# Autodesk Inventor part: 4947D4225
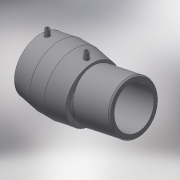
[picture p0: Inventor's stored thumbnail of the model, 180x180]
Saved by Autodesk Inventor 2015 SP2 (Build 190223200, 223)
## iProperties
Created: 2017-06
Part Number: 4947D4225
Material: Generic
Description: PLASSON ADJUSTABLE ELBOW (ONE SIDE) 225
Document SubType Name: Modeling
Designer: KIM
Mass: 8801.96 g
Surface Area: 6800.02 cm^2
Volume: 8801.96 cm^3
Density: 1 g/cm^3
Appearance: Default
Author: KIM
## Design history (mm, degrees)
derived "4947D4.ipt"
feature "Solid1::4947D4.ipt"
tag "TaggingFeature1"
body "Solid1"
other parameters: "d0" = 223.65, "d2" = 282, "d3" = 105, "d4" = 52.5, "d5" = 253.8, "d7" = 225, "d8" = 168 deg, "d10" = 42, "d11" = 14, "d29" = 141, "d30" = 15, "d31" = 85.2, "d34" = 5 deg, "d41" = 4, "d42" = 14, "d43" = 0, "d48" = 202.5, "d55" = 71.19, "d57" = 168 deg, "d62" = 3, "d63" = 0, "d65" = 426, "d66" = 225, "d67" = 202.5, "d68" = 135 deg, "d69" = 124, "d70" = 104.34, "d71" = 5.64, "d_" = 225, "L_" = 426, "L_1" = 105, "D_" = 282, "A_" = 141, "d_2" = 12, "L_0" = 148, "D_1" = 225, "L_2" = 124, "d54" = 118.65, "d59" = 273.64339
